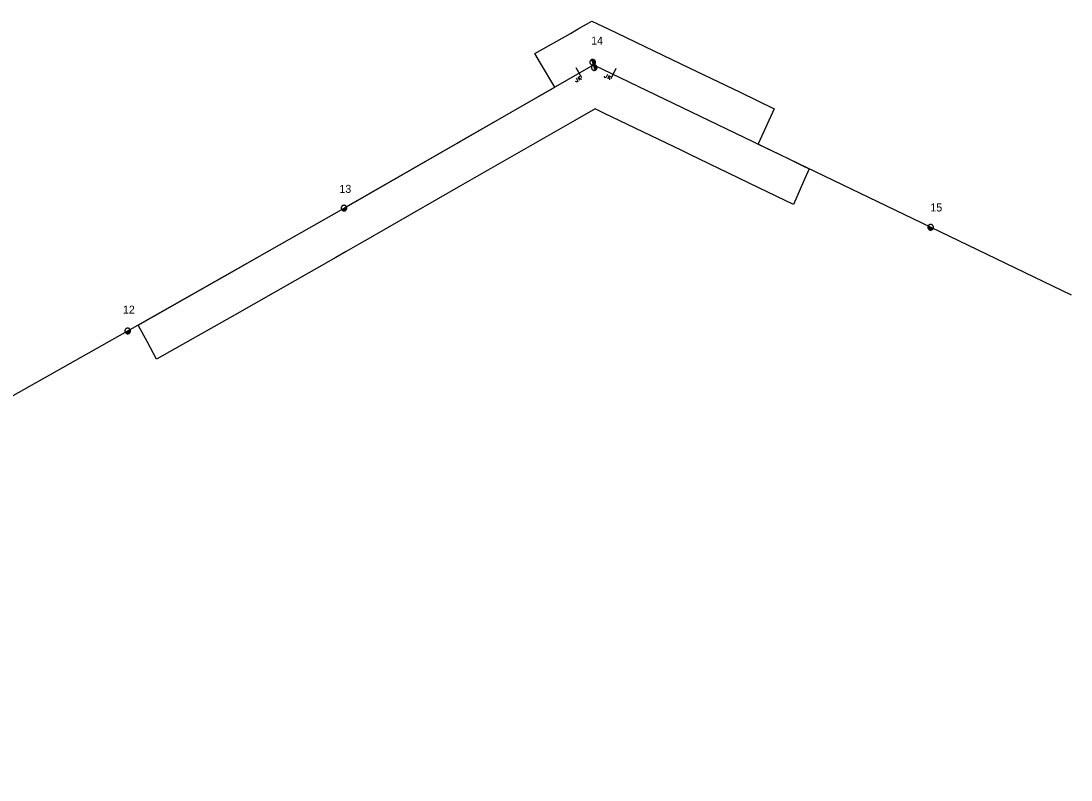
# Model space of a CAD drawing. Extents: x -536397 to -535454, y -1201642 to -1200953.
# Drawn here: x -535683.7 to -535454, y -1201351.7 to -1201185.8 of the extents above; entities that cross this region are included whole.
import ezdxf

# ---------------------------------------------------------------- set-up
doc = ezdxf.new("R2010")
doc.units = 0
for name, color, linetype in [('Vrstva 13', 7, 'Continuous'), ('Vrstva 14', 7, 'Continuous'), ('Vrstva 15', 7, 'Continuous'), ('Vrstva 18', 7, 'Continuous'), ('Vrstva 2', 7, 'Continuous'), ('Vrstva 35', 7, 'Continuous'), ('Vrstva 52', 7, 'Continuous')]:
    doc.layers.add(name, color=color, linetype=linetype)

# ---------------------------------------------------------------- blocks, each defined once
blk = doc.blocks.new('VN840')
at = {"layer": 'Vrstva 15'}
for points in [[(-0.01, 1.41), (-0.01, -1.09)], [(-1.51, -1.24), (-1.51, -1.15)], [(-1.48, -1.35), (-1.51, -1.24)], [(-1.33, -1.42), (-1.48, -1.35)], [(-1.27, -1.42), (-1.33, -1.42)], [(-1.13, -1.35), (-1.27, -1.42)], [(-1.09, -1.24), (-1.13, -1.35)], [(-1.09, -0.59), (-1.09, -1.24)], [(-0.68, -0.59), (-0.68, -1.42)], [(-0.68, -1.11), (-0.27, -0.59)], [(-0.54, -0.94), (-0.2, -1.42)]]:
    blk.add_lwpolyline(points, dxfattribs=at)
blk = doc.blocks.new('VN440')
at = {"layer": 'Vrstva 2'}
for points in [[(1.22, 0), (1.21, 0.13), (1.19, 0.25), (1.16, 0.38), (1.11, 0.5), (1.05, 0.61), (0.98, 0.72), (0.9, 0.82), (0.81, 0.91), (0.71, 0.99), (0.6, 1.06), (0.49, 1.12), (0.37, 1.16), (0.25, 1.2), (0.12, 1.22), (-0.01, 1.22), (-0.14, 1.22), (-0.26, 1.2), (-0.39, 1.16), (-0.51, 1.12), (-0.62, 1.06), (-0.73, 0.99), (-0.83, 0.91), (-0.92, 0.82), (-1, 0.72), (-1.07, 0.61), (-1.13, 0.5), (-1.18, 0.38), (-1.21, 0.25), (-1.23, 0.13), (-1.24, 0), (-1.23, -0.13), (-1.21, -0.26), (-1.18, -0.38), (-1.13, -0.5), (-1.07, -0.62), (-1, -0.73), (-0.92, -0.83), (-0.83, -0.92), (-0.73, -1), (-0.62, -1.07), (-0.51, -1.13), (-0.39, -1.17), (-0.26, -1.2), (-0.14, -1.23), (-0.01, -1.23), (0.12, -1.23), (0.25, -1.2), (0.37, -1.17), (0.49, -1.13), (0.6, -1.07), (0.71, -1), (0.81, -0.92), (0.9, -0.83), (0.98, -0.73), (1.05, -0.62), (1.11, -0.5), (1.16, -0.38), (1.19, -0.26), (1.21, -0.13), (1.22, 0)], [(-1.24, 0), (1.22, 0)], [(-1.18, -0.34), (1.1, -0.34)], [(-1.01, -0.63), (0.97, -0.63)], [(-0.74, -0.92), (0.68, -0.92)]]:
    blk.add_lwpolyline(points, dxfattribs=at)
blk = doc.blocks.new('VN450')
at = {"layer": 'Vrstva 2'}
for points in [[(0, 0), (-0.01, 0.13), (-0.03, 0.25), (-0.06, 0.38), (-0.11, 0.5), (-0.16, 0.61), (-0.23, 0.72), (-0.31, 0.82), (-0.4, 0.91), (-0.5, 0.99), (-0.61, 1.06), (-0.72, 1.11), (-0.84, 1.16), (-0.97, 1.19), (-1.09, 1.21), (-1.22, 1.22), (-1.35, 1.21), (-1.47, 1.19), (-1.59, 1.16), (-1.71, 1.11), (-1.83, 1.06), (-1.93, 0.99), (-2.03, 0.91), (-2.12, 0.82), (-2.2, 0.72), (-2.27, 0.61), (-2.33, 0.5), (-2.38, 0.38), (-2.41, 0.25), (-2.43, 0.13), (-2.44, 0), (-2.43, -0.13), (-2.41, -0.25), (-2.38, -0.38), (-2.33, -0.5), (-2.27, -0.61), (-2.2, -0.72), (-2.12, -0.82), (-2.03, -0.91), (-1.93, -0.99), (-1.83, -1.06), (-1.71, -1.11), (-1.59, -1.16), (-1.47, -1.19), (-1.35, -1.21), (-1.22, -1.22), (-1.09, -1.21), (-0.97, -1.19), (-0.84, -1.16), (-0.72, -1.11), (-0.61, -1.06), (-0.5, -0.99), (-0.4, -0.91), (-0.31, -0.82), (-0.23, -0.72), (-0.16, -0.61), (-0.11, -0.5), (-0.06, -0.38), (-0.03, -0.25), (-0.01, -0.13), (0, 0)], [(-2.44, 0), (2.44, 0)], [(2.44, 0), (2.43, 0.13), (2.41, 0.25), (2.38, 0.38), (2.33, 0.5), (2.27, 0.61), (2.2, 0.72), (2.12, 0.82), (2.03, 0.91), (1.94, 0.99), (1.83, 1.06), (1.71, 1.11), (1.6, 1.16), (1.47, 1.19), (1.35, 1.21), (1.22, 1.22), (1.09, 1.21), (0.97, 1.19), (0.84, 1.16), (0.72, 1.11), (0.61, 1.06), (0.5, 0.99), (0.4, 0.91), (0.31, 0.82), (0.23, 0.72), (0.16, 0.61), (0.11, 0.5), (0.06, 0.38), (0.03, 0.25), (0.01, 0.13), (0, 0), (0.01, -0.13), (0.03, -0.25), (0.06, -0.38), (0.11, -0.5), (0.16, -0.61), (0.23, -0.72), (0.31, -0.82), (0.4, -0.91), (0.5, -0.99), (0.61, -1.06), (0.72, -1.11), (0.84, -1.16), (0.97, -1.19), (1.09, -1.21), (1.22, -1.22), (1.35, -1.21), (1.47, -1.19), (1.6, -1.16), (1.71, -1.11), (1.83, -1.06), (1.94, -0.99), (2.03, -0.91), (2.12, -0.82), (2.2, -0.72), (2.27, -0.61), (2.33, -0.5), (2.38, -0.38), (2.41, -0.25), (2.43, -0.13), (2.44, 0)], [(-2.4, -0.31), (-0.04, -0.31)], [(-2.26, -0.61), (-0.17, -0.61)], [(-2.01, -0.92), (-0.42, -0.92)], [(0.04, -0.31), (2.4, -0.31)], [(0.17, -0.61), (2.27, -0.61)], [(0.42, -0.92), (2.02, -0.92)]]:
    blk.add_lwpolyline(points, dxfattribs=at)

msp = doc.modelspace()

# ---------------------------------------------------------------- linework, layer by layer
at = {"layer": 'Vrstva 35'}
msp.add_lwpolyline([(-535558.78, -1201185.79), (-535555.23, -1201187.5), (-535543.26, -1201193.26), (-535537.5, -1201196.03), (-535526.38, -1201201.38), (-535518.93, -1201204.97), (-535522.32, -1201212.5), (-535522.42, -1201212.72), (-535515.87, -1201215.87), (-535512.5, -1201217.5), (-535511.28, -1201218.08), (-535512.5, -1201220.9), (-535514.67, -1201225.89), (-535522.24, -1201222.24), (-535537.5, -1201214.9), (-535539.12, -1201214.12), (-535542.48, -1201212.5), (-535555.99, -1201205.99), (-535558.08, -1201204.99), (-535562.5, -1201207.53), (-535571.17, -1201212.5), (-535587.5, -1201221.86), (-535608.78, -1201234.07), (-535609.45, -1201234.45), (-535612.5, -1201236.18), (-535614.82, -1201237.5), (-535637.5, -1201250.38), (-535654.01, -1201259.75), (-535656.02, -1201256.02), (-535658.05, -1201252.27), (-535644.68, -1201244.68), (-535637.5, -1201240.6), (-535632.03, -1201237.5), (-535612.99, -1201226.69), (-535612.5, -1201226.41), (-535588.25, -1201212.5), (-535587.5, -1201212.07), (-535586.49, -1201211.49), (-535566.86, -1201200.23), (-535569.99, -1201194.99), (-535571.23, -1201192.93), (-535563.49, -1201188.49), (-535562.5, -1201187.92), (-535561.76, -1201187.5)], close=True, dxfattribs=at)
at = {"layer": 'Vrstva 52'}
msp.add_lwpolyline([(-535821.22, -1201351.74), (-535780.71, -1201325.35), (-535744.04, -1201301.36), (-535707.01, -1201279.85), (-535660.31, -1201253.55), (-535612.99, -1201226.69), (-535558.43, -1201195.39), (-535484.67, -1201230.89), (-535453.98, -1201245.69)], dxfattribs=at)

# ---------------------------------------------------------------- block references
at = {"layer": 'Vrstva 13'}
for name, p, xscale, yscale, rotation in [('VN450', (-535558.43, -1201195.39), 0.5000000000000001, 0.5, 106.30393057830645), ('VN440', (-535612.99, -1201226.69), 0.5, 0.5, 29.42619153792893), ('VN440', (-535484.67, -1201230.89), 0.5, 0.5000000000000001, -25.701188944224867), ('VN440', (-535660.31, -1201253.55), 0.5, 0.5, 29.387286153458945)]:
    msp.add_blockref(name, p, dxfattribs=dict(at, xscale=xscale, yscale=yscale, rotation=rotation))
at = {"layer": 'Vrstva 18'}
for p, rotation in [((-535561.57, -1201197.19), 29.842047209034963), ((-535554.15, -1201197.45), -25.701077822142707)]:
    msp.add_blockref('VN840', p, dxfattribs=dict(at, rotation=rotation))

# ---------------------------------------------------------------- texts
at = {"layer": 'Vrstva 14'}
for s, p in [('14', (-535558.94, -1201190.94)), ('13', (-535614.02, -1201223.37)), ('15', (-535484.75, -1201227.44)), ('12', (-535661.37, -1201249.77))]:
    msp.add_text(s, height=1.75, dxfattribs=at).set_placement(p)

doc.saveas('drawing.dxf')
